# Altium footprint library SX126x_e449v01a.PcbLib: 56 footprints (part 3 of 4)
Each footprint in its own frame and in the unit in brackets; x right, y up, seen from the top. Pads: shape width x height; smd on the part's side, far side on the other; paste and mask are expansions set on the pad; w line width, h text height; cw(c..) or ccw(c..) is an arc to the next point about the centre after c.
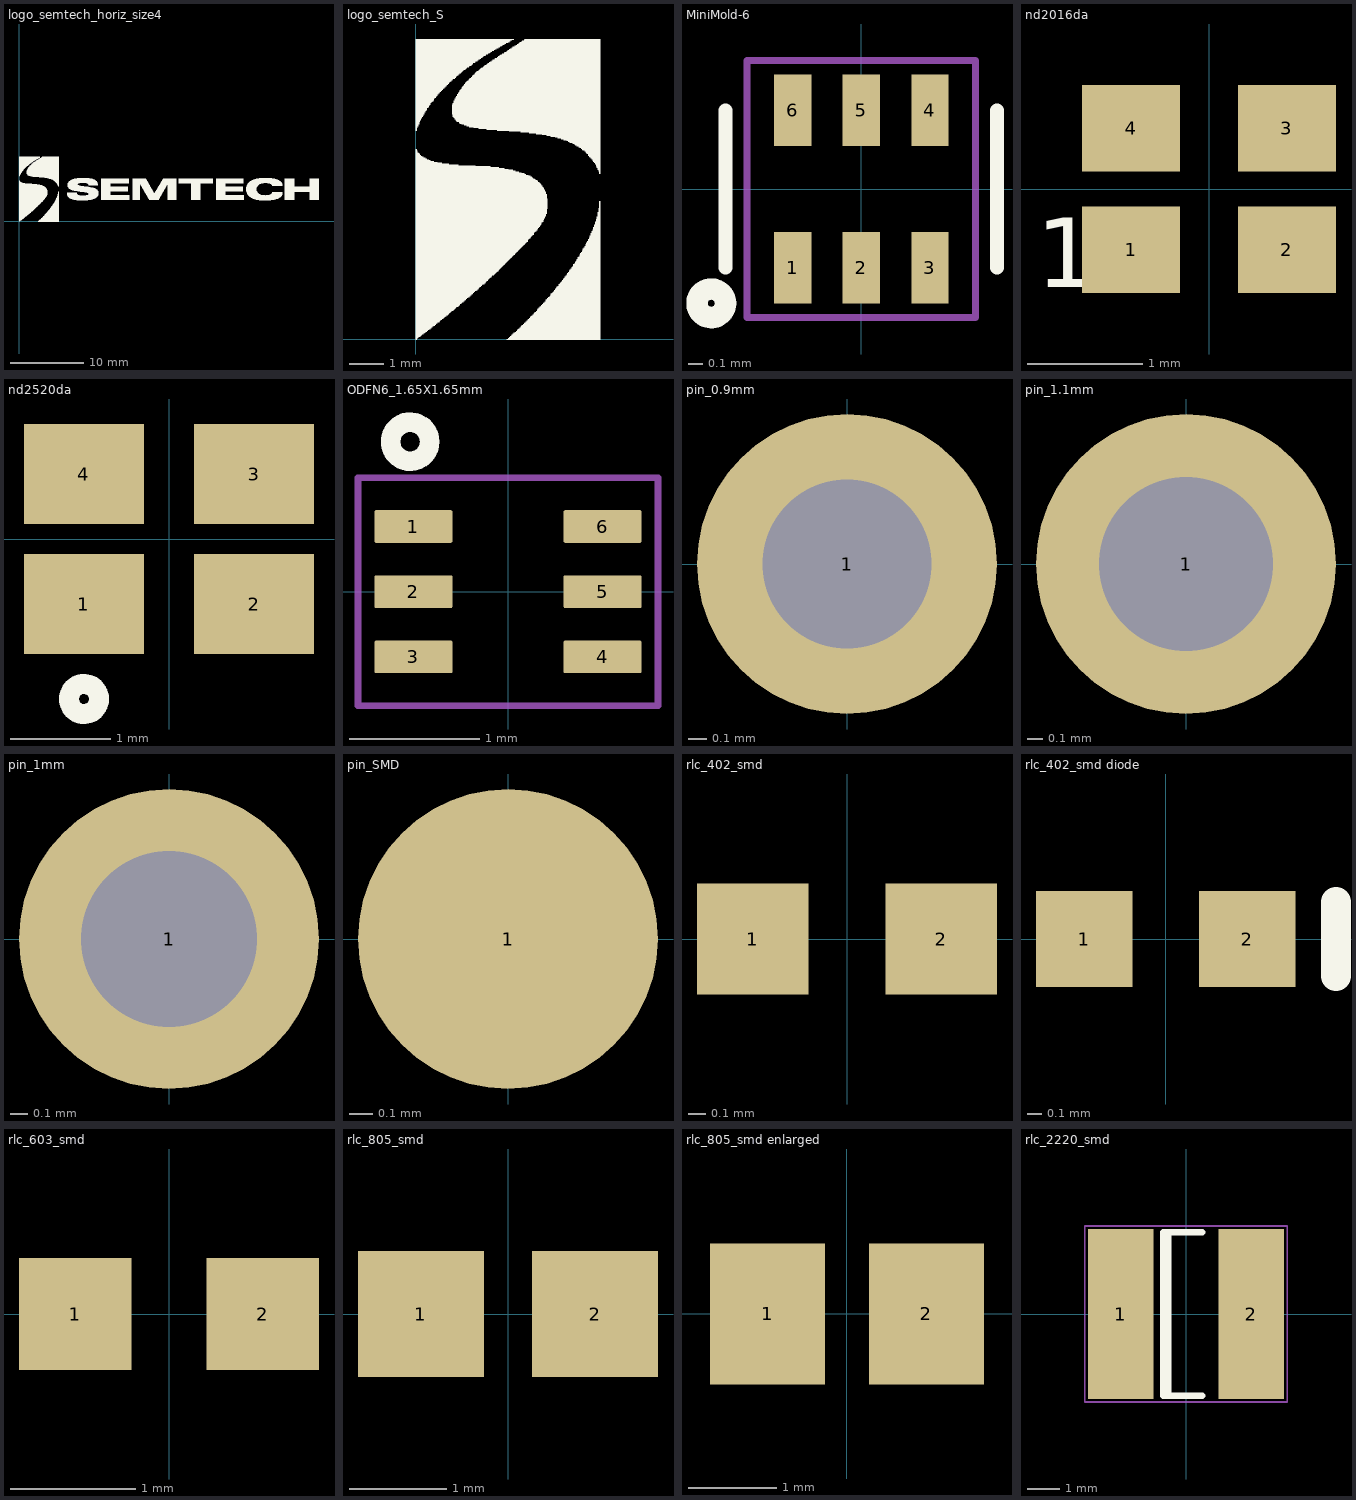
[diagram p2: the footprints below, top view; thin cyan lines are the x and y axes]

## logo_semtech_horiz_size4 [mm] "Logo semtech horizontal - size4 - XL"
Top Overlay:
  drawing of 1852 lines, arcs and shapes, not listed

## logo_semtech_S [mm] "Logo semtech S size4 - XL"
Top Overlay:
  drawing of 642 lines, arcs and shapes, not listed

## MiniMold-6 [mm] "MiniMold-6 Package 1.5x1.1mm"
height 0.55
pads (6):
  rect 0.26x0.5 smd mask+0.05: 1(-0.48,-0.55) 2(0,-0.55) 3(0.48,-0.55) 4(0.48,0.55) 5(0,0.55) 6(-0.48,0.55)
Top Overlay:
  circle w0.15: c-1.05,-0.8 r0.1
  lines w0.1: -0.95,-0.55 -0.95,0.55 ; 0.95,-0.55 0.95,0.55
Mechanical 15:
  lines w0.05: -0.8,-0.9 0.8,-0.9 0.8,0.9 -0.8,0.9 -0.8,-0.9
3D body: height 1, standoff 0, extent -0.75,-0.55 0.75,0.55

## nd2016da [mm] "Crystal SMD 2.0x1.6mm"
height 0.55
pads (4):
  rect 0.85x0.75 smd mask+0.05: 1(-0.675,-0.525) 2(0.675,-0.525) 3(0.675,0.525) 4(-0.675,0.525)
Top Overlay:
  text "1" at -1.5,-0.85 h0.6
3D body: height 1, standoff 0, extent -1,-0.8 1,0.8

## nd2520da [mm] "Crystal SMD 2.5x2.0mm"
height 0.7
pads (4):
  rect 1.2x1 smd mask+0.05: 1(-0.85,-0.65) 2(0.85,-0.65) 3(0.85,0.65) 4(-0.85,0.65)
Top Overlay:
  circle w0.2: c-0.85,-1.6 r0.15
3D body: height 1, standoff 0, extent -1.25,-1 1.25,1

## ODFN6_1.65X1.65mm [mm] "6 Leads, Body 1.65x1.65mm, pitch 0.5mm, ODFN6"
height 1
pads (6):
  rrect10% 0.6x0.25 smd paste+0 mask+0.05: 1(-0.725,0.5) 2(-0.725,0) 3(-0.725,-0.5) 4(0.725,-0.5) 5(0.725,0) 6(0.725,0.5)
Top Overlay:
  circle w0.15: c-0.75,1.15 r0.15
Mechanical 15:
  lines w0.05: -1.15,-0.875 -1.15,0.875 1.15,0.875 1.15,-0.875 -1.15,-0.875
3D body: height 1, standoff 0, extent -0.825,-0.825 0.825,0.825

## pin_0.9mm [mm] "Generic Pin 0.9mm; 1 Lead"
height 1
pads (1):
  round 1.6 hole 0.9 mask+0.05: 1(0,0)

## pin_1.1mm [mm] "Generic Pin 1.1mm; 1 Lead"
height 1
pads (1):
  round 1.9 hole 1.1 mask+0.05: 1(0,0)

## pin_1mm [mm] "Generic Pin 1.1mm; 1 Lead"
height 1
pads (1):
  round 1.7 hole 1 paste+0 mask+0.05: 1(0,0)

## pin_SMD [mm] "Generic Pin; 1 pin SMD"
height 0.5
pads (1):
  round 1.27 smd paste-1 mask+0.05: 1(0,0)

## rlc_402_smd [mm] "Chip SMD component 402; Body 1.0 x 0.5 mm (LxW typ)"
height 0.8
pads (2):
  rect 0.65x0.65 smd mask+0.05: 1(-0.55,0) 2(0.55,0)
3D body: height 0.8, standoff 0.2, extent -0.875,-0.325 0.875,0.325

## rlc_402_smd diode [mm] "Chip SMD component 402; Body 1.0 x 0.5 mm (LxW typ)"
height 0.8
pads (2):
  rect 0.65x0.65 smd mask+0.05: 1(-0.55,0) 2(0.55,0)
Top Overlay:
  lines w0.2: 1.15,-0.25 1.15,0.25

## rlc_603_smd [mm] "Chip SMD component 603; Body 1.6 x 0.8mm (LxW typ)"
height 1
pads (2):
  rect 0.9x0.9 smd paste+0 mask+0.05: 1(-0.75,0) 2(0.75,0)

## rlc_805_smd [mm] "Chip SMD component 805; Body 2.0 x 1.25 mm (LxW typ)"
height 1.4
pads (2):
  rect 1.3x1.3 smd mask+0.05: 1(-0.9,0) 2(0.9,0)

## rlc_805_smd enlarged [mm] "Chip SMD component 805; Body 2.0 x 1.25 mm (LxW typ)"
height 1.4
pads (2):
  rect 1.3x1.6 smd mask+0.05: 1(-0.9,0) 2(0.9,0)

## rlc_2220_smd [mm] "Chip SMD component ; Body 5.7 x 5.0 mm (LxW typ)"
height 5
pads (2):
  rect 2x5.2 smd mask+0.05: 1(-2,0) 2(2,0)
Top Overlay:
  lines w0.2: -0.55,-2.5 -0.55,2.5 ; 0.5,-2.5 -0.7,-2.5 -0.7,2.5 0.5,2.5
Mechanical 15:
  lines w0.05: -3.1,-2.7 3.1,-2.7 3.1,2.7 -3.1,2.7 -3.1,-2.7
